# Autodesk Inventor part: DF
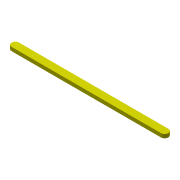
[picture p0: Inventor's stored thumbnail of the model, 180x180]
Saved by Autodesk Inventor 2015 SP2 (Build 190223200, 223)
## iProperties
Created: 2019-08
Part Number: DF
Material: 一般
Document SubType Name: Modeling
Designer: Kuan_Lun Hsu
Density: 1 g/cm^3
Appearance: Smooth - Yellow
Mass: 0.43927 g
Surface Area: 6.30686 cm^2
Volume: 0.43927 cm^3
Author: Kuan_Lun Hsu
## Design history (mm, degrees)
sketch "草圖1"
  geometry: L1 (0, 0)-(40, 0); L2 (0, -2.5)-(40, -2.5); L3 (40, 2.5)-(0, 2.5); A1 r 2.5 centre (0, 0) between (0, 2.5) and (0, -2.5); A2 r 2.5 centre (40, 0) between (40, -2.5) and (40, 2.5); 1 further point
  constraints: 8 end point, 4 point on circle, 4 tangent, 2 centre point, 1 horizontal, 1 midpoint, 1 parallel
  dimensions: "d0" = 40 distance of L1.start L1.end (= DF_); "d1" = 5 distance between parallel lines of L2 L3 (= w_)
extrude "擠出1" new body sketch "草圖1" distance "d2" = 2 (= t_); taper "d3" = 0 deg
node "實體1"
other parameters: "DF_" = 40 [user parameter; used in 1 equation term], "w_" = 5 [user parameter; used in 1 equation term], "t_" = 2 [user parameter; used in 1 equation term]
